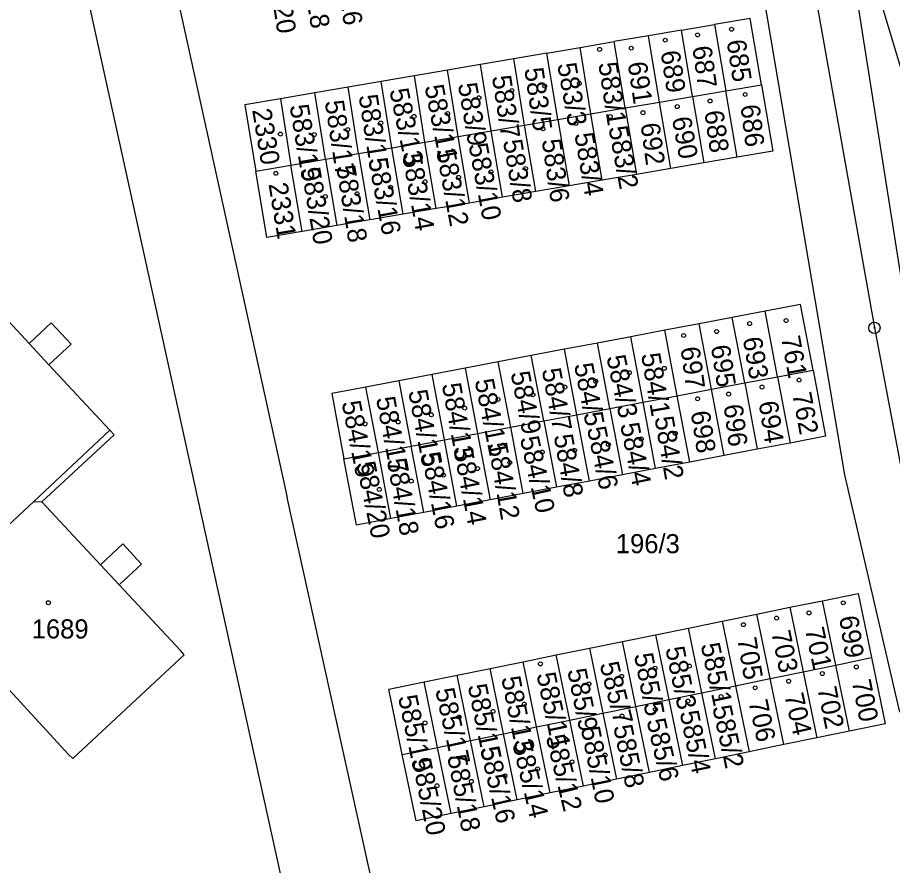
# Model space of a CAD drawing. Extents: x -735249 to -729401, y -1124843 to -1121828.
# Drawn here: x -732956.9 to -732879.1, y -1123958.8 to -1123883.4 of the extents above; entities that cross this region are included whole.
import ezdxf

# ---------------------------------------------------------------- set-up
doc = ezdxf.new("R2010")
doc.units = 0
for name, color, linetype in [('Vrstva 1', 7, 'Continuous'), ('Vrstva 16', 7, 'Continuous'), ('Vrstva 18', 7, 'Continuous'), ('Vrstva 19', 7, 'Continuous'), ('Vrstva 25', 7, 'Continuous'), ('Vrstva 4', 7, 'Continuous')]:
    doc.layers.add(name, color=color, linetype=linetype)

msp = doc.modelspace()

# ---------------------------------------------------------------- linework, layer by layer
at = {"layer": 'Vrstva 1'}
for points in [[(-732886.84, -1123876.47), (-732880.71, -1123910.98), (-732875.49, -1123938.55)], [(-732883.18, -1123876.03), (-732877.7, -1123910.61)], [(-732881.98, -1123875.88), (-732871.76, -1123909.89)], [(-732878.45, -1123945.16), (-732883.33, -1123924.04), (-732891.19, -1123877.61)], [(-732942.93, -1123880.58), (-732932.93, -1123926.08)], [(-732940.57, -1123927.62), (-732950.53, -1123882.29)], [(-732891.77, -1123883.46), (-732894.93, -1123884)], [(-732890.77, -1123889.36), (-732891.77, -1123883.46)], [(-732897.86, -1123884.5), (-732894.93, -1123884)], [(-732894.93, -1123884), (-732893.94, -1123889.9)], [(-732900.82, -1123885.01), (-732903.85, -1123885.53)], [(-732897.86, -1123884.5), (-732900.82, -1123885.01)], [(-732899.83, -1123890.91), (-732900.82, -1123885.01)], [(-732896.88, -1123890.41), (-732897.86, -1123884.5)], [(-732906.88, -1123886.05), (-732903.85, -1123885.53)], [(-732902.88, -1123891.43), (-732903.85, -1123885.53)], [(-732909.84, -1123886.55), (-732912.79, -1123887.06)], [(-732909.84, -1123886.55), (-732906.88, -1123886.05)], [(-732908.88, -1123892.46), (-732909.84, -1123886.55)], [(-732905.93, -1123891.95), (-732906.88, -1123886.05)], [(-732912.79, -1123887.06), (-732915.76, -1123887.57)], [(-732911.84, -1123892.96), (-732912.79, -1123887.06)], [(-732918.68, -1123888.07), (-732921.63, -1123888.57)], [(-732915.76, -1123887.57), (-732918.68, -1123888.07)], [(-732917.74, -1123893.97), (-732918.68, -1123888.07)], [(-732914.8, -1123893.47), (-732915.76, -1123887.57)], [(-732921.63, -1123888.57), (-732924.57, -1123889.07)], [(-732920.7, -1123894.47), (-732921.63, -1123888.57)], [(-732927.52, -1123889.58), (-732930.47, -1123890.08)], [(-732924.57, -1123889.07), (-732927.52, -1123889.58)], [(-732926.6, -1123895.48), (-732927.52, -1123889.58)], [(-732923.64, -1123894.98), (-732924.57, -1123889.07)], [(-732893.94, -1123889.9), (-732890.77, -1123889.36)], [(-732890.77, -1123889.36), (-732889.76, -1123895.27)], [(-732930.47, -1123890.08), (-732933.54, -1123890.61)], [(-732929.54, -1123895.98), (-732930.47, -1123890.08)], [(-732899.83, -1123890.91), (-732896.88, -1123890.41)], [(-732896.88, -1123890.41), (-732893.94, -1123889.9)], [(-732896.88, -1123890.41), (-732895.87, -1123896.31)], [(-732892.93, -1123895.81), (-732893.94, -1123889.9)], [(-732933.54, -1123890.61), (-732936.7, -1123891.15)], [(-732936.7, -1123891.15), (-732935.72, -1123897.05)], [(-732933.54, -1123890.61), (-732932.62, -1123896.51)], [(-732902.88, -1123891.43), (-732899.83, -1123890.91)], [(-732898.82, -1123896.82), (-732899.83, -1123890.91)], [(-732908.88, -1123892.46), (-732905.93, -1123891.95)], [(-732905.93, -1123891.95), (-732902.88, -1123891.43)], [(-732904.92, -1123897.86), (-732905.93, -1123891.95)], [(-732902.88, -1123891.43), (-732901.87, -1123897.34)], [(-732911.84, -1123892.96), (-732908.88, -1123892.46)], [(-732908.88, -1123892.46), (-732907.87, -1123898.36)], [(-732917.74, -1123893.97), (-732914.8, -1123893.47)], [(-732914.8, -1123893.47), (-732911.84, -1123892.96)], [(-732913.79, -1123899.37), (-732914.8, -1123893.47)], [(-732910.83, -1123898.87), (-732911.84, -1123892.96)], [(-732920.7, -1123894.47), (-732917.74, -1123893.97)], [(-732916.73, -1123899.88), (-732917.74, -1123893.97)], [(-732926.6, -1123895.48), (-732923.64, -1123894.98)], [(-732923.64, -1123894.98), (-732920.7, -1123894.47)], [(-732922.63, -1123900.88), (-732923.64, -1123894.98)], [(-732919.69, -1123900.38), (-732920.7, -1123894.47)], [(-732929.54, -1123895.98), (-732926.6, -1123895.48)], [(-732926.6, -1123895.48), (-732925.59, -1123901.39)], [(-732892.93, -1123895.81), (-732895.87, -1123896.31)], [(-732889.76, -1123895.27), (-732892.93, -1123895.81)], [(-732935.72, -1123897.05), (-732932.62, -1123896.51)], [(-732932.62, -1123896.51), (-732929.54, -1123895.98)], [(-732931.61, -1123902.42), (-732932.62, -1123896.51)], [(-732929.54, -1123895.98), (-732928.53, -1123901.89)], [(-732895.87, -1123896.31), (-732898.82, -1123896.82)], [(-732934.74, -1123902.95), (-732935.72, -1123897.05)], [(-732901.87, -1123897.34), (-732904.92, -1123897.86)], [(-732898.82, -1123896.82), (-732901.87, -1123897.34)], [(-732904.92, -1123897.86), (-732907.87, -1123898.36)], [(-732910.83, -1123898.87), (-732913.79, -1123899.37)], [(-732907.87, -1123898.36), (-732910.83, -1123898.87)], [(-732913.79, -1123899.37), (-732916.73, -1123899.88)], [(-732919.69, -1123900.38), (-732922.63, -1123900.88)], [(-732916.73, -1123899.88), (-732919.69, -1123900.38)], [(-732922.63, -1123900.88), (-732925.59, -1123901.39)], [(-732928.53, -1123901.89), (-732931.61, -1123902.42)], [(-732925.59, -1123901.39), (-732928.53, -1123901.89)], [(-732931.61, -1123902.42), (-732934.74, -1123902.95)], [(-732961.35, -1123906.5), (-732955.9, -1123912.36)], [(-732887.28, -1123908.9), (-732890.43, -1123909.5)], [(-732886.17, -1123914.73), (-732887.28, -1123908.9)], [(-732890.43, -1123909.5), (-732893.36, -1123910.05)], [(-732889.32, -1123915.33), (-732890.43, -1123909.5)], [(-732955.9, -1123912.36), (-732953.93, -1123910.53)], [(-732953.93, -1123910.53), (-732952.15, -1123912.43)], [(-732896.31, -1123910.61), (-732899.36, -1123911.19)], [(-732893.36, -1123910.05), (-732896.31, -1123910.61)], [(-732895.2, -1123916.44), (-732896.31, -1123910.61)], [(-732892.25, -1123915.88), (-732893.36, -1123910.05)], [(-732899.36, -1123911.19), (-732902.39, -1123911.77)], [(-732898.25, -1123917.02), (-732899.36, -1123911.19)], [(-732902.39, -1123911.77), (-732905.34, -1123912.33)], [(-732901.29, -1123917.59), (-732902.39, -1123911.77)], [(-732952.15, -1123912.43), (-732954.13, -1123914.27)], [(-732908.28, -1123912.88), (-732911.23, -1123913.44)], [(-732905.34, -1123912.33), (-732908.28, -1123912.88)], [(-732907.17, -1123918.71), (-732908.28, -1123912.88)], [(-732904.24, -1123918.15), (-732905.34, -1123912.33)], [(-732911.23, -1123913.44), (-732914.19, -1123914.01)], [(-732910.1, -1123919.26), (-732911.23, -1123913.44)], [(-732954.13, -1123914.27), (-732948.71, -1123920.08)], [(-732917.12, -1123914.56), (-732920.06, -1123915.12)], [(-732914.19, -1123914.01), (-732917.12, -1123914.56)], [(-732917.12, -1123914.56), (-732916.01, -1123920.38)], [(-732913.05, -1123919.82), (-732914.19, -1123914.01)], [(-732920.06, -1123915.12), (-732923, -1123915.68)], [(-732918.96, -1123920.94), (-732920.06, -1123915.12)], [(-732892.25, -1123915.88), (-732889.32, -1123915.33)], [(-732889.32, -1123915.33), (-732886.17, -1123914.73)], [(-732889.32, -1123915.33), (-732888.2, -1123921.22)], [(-732886.17, -1123914.73), (-732885.05, -1123920.62)], [(-732923, -1123915.68), (-732925.95, -1123916.24)], [(-732923, -1123915.68), (-732921.9, -1123921.5)], [(-732895.2, -1123916.44), (-732892.25, -1123915.88)], [(-732892.25, -1123915.88), (-732891.14, -1123921.77)], [(-732925.95, -1123916.24), (-732928.97, -1123916.81)], [(-732928.97, -1123916.81), (-732927.89, -1123922.63)], [(-732924.83, -1123922.05), (-732925.95, -1123916.24)], [(-732898.25, -1123917.02), (-732895.2, -1123916.44)], [(-732894.08, -1123922.33), (-732895.2, -1123916.44)], [(-732904.24, -1123918.15), (-732901.29, -1123917.59)], [(-732901.29, -1123917.59), (-732898.25, -1123917.02)], [(-732900.18, -1123923.48), (-732901.29, -1123917.59)], [(-732897.13, -1123922.91), (-732898.25, -1123917.02)], [(-732907.17, -1123918.71), (-732904.24, -1123918.15)], [(-732904.24, -1123918.15), (-732903.12, -1123924.04)], [(-732913.05, -1123919.82), (-732910.1, -1123919.26)], [(-732910.1, -1123919.26), (-732907.17, -1123918.71)], [(-732910.1, -1123919.26), (-732908.98, -1123925.15)], [(-732906.06, -1123924.6), (-732907.17, -1123918.71)], [(-732916.01, -1123920.38), (-732913.05, -1123919.82)], [(-732911.94, -1123925.71), (-732913.05, -1123919.82)], [(-732948.34, -1123920.48), (-732954.76, -1123926.44)], [(-732948.71, -1123920.08), (-732948.34, -1123920.48)], [(-732918.96, -1123920.94), (-732916.01, -1123920.38)], [(-732916.01, -1123920.38), (-732914.89, -1123926.27)], [(-732885.05, -1123920.62), (-732888.2, -1123921.22)], [(-732924.83, -1123922.05), (-732921.9, -1123921.5)], [(-732921.9, -1123921.5), (-732918.96, -1123920.94)], [(-732920.78, -1123927.39), (-732921.9, -1123921.5)], [(-732917.85, -1123926.83), (-732918.96, -1123920.94)], [(-732888.2, -1123921.22), (-732891.14, -1123921.77)], [(-732927.89, -1123922.63), (-732924.83, -1123922.05)], [(-732923.72, -1123927.94), (-732924.83, -1123922.05)], [(-732894.08, -1123922.33), (-732897.13, -1123922.91)], [(-732891.14, -1123921.77), (-732894.08, -1123922.33)], [(-732926.77, -1123928.52), (-732927.89, -1123922.63)], [(-732897.13, -1123922.91), (-732900.18, -1123923.48)], [(-732900.18, -1123923.48), (-732903.12, -1123924.04)], [(-732906.06, -1123924.6), (-732908.98, -1123925.15)], [(-732903.12, -1123924.04), (-732906.06, -1123924.6)], [(-732908.98, -1123925.15), (-732911.94, -1123925.71)], [(-732920.95, -1123980.45), (-732932.93, -1123926.08)], [(-732914.89, -1123926.27), (-732917.85, -1123926.83)], [(-732911.94, -1123925.71), (-732914.89, -1123926.27)], [(-732958.21, -1123928.96), (-732955.46, -1123926.41)], [(-732955.46, -1123926.41), (-732954.76, -1123926.44)], [(-732949.54, -1123932.04), (-732954.76, -1123926.44)], [(-732917.85, -1123926.83), (-732920.78, -1123927.39)], [(-732922.61, -1124019.23), (-732926.9, -1124007.81), (-732928.66, -1124002.14), (-732929.71, -1123998.65), (-732925.26, -1123994.52), (-732927.83, -1123984.85), (-732930.58, -1123972.96), (-732940.57, -1123927.62)], [(-732920.78, -1123927.39), (-732923.72, -1123927.94)], [(-732923.72, -1123927.94), (-732926.77, -1123928.52)], [(-732947.57, -1123930.2), (-732949.54, -1123932.04)], [(-732945.9, -1123931.99), (-732947.57, -1123930.2)], [(-732947.88, -1123933.82), (-732945.9, -1123931.99)], [(-732942.44, -1123939.68), (-732947.88, -1123933.82)], [(-732885.32, -1123935.24), (-732882.15, -1123934.59)], [(-732882.15, -1123934.59), (-732880.98, -1123940.3)], [(-732964.95, -1123935.26), (-732952.38, -1123948.92)], [(-732888.24, -1123935.83), (-732885.32, -1123935.24)], [(-732884.14, -1123940.96), (-732885.32, -1123935.24)], [(-732891.17, -1123936.43), (-732888.24, -1123935.83)], [(-732888.24, -1123935.83), (-732887.05, -1123941.56)], [(-732897.24, -1123937.67), (-732894.26, -1123937.06)], [(-732894.26, -1123937.06), (-732891.17, -1123936.43)], [(-732894.26, -1123937.06), (-732893.07, -1123942.81)], [(-732889.99, -1123942.17), (-732891.17, -1123936.43)], [(-732900.18, -1123938.27), (-732897.24, -1123937.67)], [(-732896.06, -1123943.42), (-732897.24, -1123937.67)], [(-732903.12, -1123938.87), (-732900.18, -1123938.27)], [(-732900.18, -1123938.27), (-732899, -1123944.03)], [(-732909.01, -1123940.07), (-732906.06, -1123939.47)], [(-732906.06, -1123939.47), (-732903.12, -1123938.87)], [(-732906.06, -1123939.47), (-732904.87, -1123945.25)], [(-732901.93, -1123944.64), (-732903.12, -1123938.87)], [(-732952.01, -1123949.26), (-732942.1, -1123940.05)], [(-732942.1, -1123940.05), (-732942.44, -1123939.68)], [(-732911.96, -1123940.67), (-732909.01, -1123940.07)], [(-732907.81, -1123945.85), (-732909.01, -1123940.07)], [(-732914.9, -1123941.27), (-732911.96, -1123940.67)], [(-732910.76, -1123946.46), (-732911.96, -1123940.67)], [(-732887.05, -1123941.56), (-732884.14, -1123940.96)], [(-732884.14, -1123940.96), (-732880.98, -1123940.3)], [(-732882.92, -1123946.83), (-732884.14, -1123940.96)], [(-732880.98, -1123940.3), (-732879.76, -1123946.18)], [(-732917.82, -1123941.87), (-732914.9, -1123941.27)], [(-732913.7, -1123947.07), (-732914.9, -1123941.27)], [(-732889.99, -1123942.17), (-732887.05, -1123941.56)], [(-732887.05, -1123941.56), (-732885.83, -1123947.44)], [(-732923.89, -1123943.11), (-732920.77, -1123942.47)], [(-732920.77, -1123942.47), (-732917.82, -1123941.87)], [(-732919.57, -1123948.29), (-732920.77, -1123942.47)], [(-732916.63, -1123947.68), (-732917.82, -1123941.87)], [(-732893.07, -1123942.81), (-732889.99, -1123942.17)], [(-732888.77, -1123948.04), (-732889.99, -1123942.17)], [(-732922.7, -1123948.93), (-732923.89, -1123943.11)], [(-732896.06, -1123943.42), (-732893.07, -1123942.81)], [(-732893.07, -1123942.81), (-732891.85, -1123948.68)], [(-732901.93, -1123944.64), (-732899, -1123944.03)], [(-732899, -1123944.03), (-732896.06, -1123943.42)], [(-732899, -1123944.03), (-732897.78, -1123949.91)], [(-732894.84, -1123949.3), (-732896.06, -1123943.42)], [(-732904.87, -1123945.25), (-732901.93, -1123944.64)], [(-732900.72, -1123950.52), (-732901.93, -1123944.64)], [(-732907.81, -1123945.85), (-732904.87, -1123945.25)], [(-732904.87, -1123945.25), (-732903.66, -1123951.12)], [(-732913.7, -1123947.07), (-732910.76, -1123946.46)], [(-732910.76, -1123946.46), (-732907.81, -1123945.85)], [(-732909.54, -1123952.34), (-732910.76, -1123946.46)], [(-732906.59, -1123951.73), (-732907.81, -1123945.85)], [(-732879.76, -1123946.18), (-732882.92, -1123946.83)], [(-732916.63, -1123947.68), (-732913.7, -1123947.07)], [(-732912.48, -1123952.95), (-732913.7, -1123947.07)], [(-732882.92, -1123946.83), (-732885.83, -1123947.44)], [(-732919.57, -1123948.29), (-732916.63, -1123947.68)], [(-732915.42, -1123953.56), (-732916.63, -1123947.68)], [(-732888.77, -1123948.04), (-732891.85, -1123948.68)], [(-732885.83, -1123947.44), (-732888.77, -1123948.04)], [(-732922.7, -1123948.93), (-732919.57, -1123948.29)], [(-732918.36, -1123954.16), (-732919.57, -1123948.29)], [(-732891.85, -1123948.68), (-732894.84, -1123949.3)], [(-732952.38, -1123948.92), (-732952.01, -1123949.26)], [(-732921.48, -1123954.81), (-732922.7, -1123948.93)], [(-732894.84, -1123949.3), (-732897.78, -1123949.91)], [(-732897.78, -1123949.91), (-732900.72, -1123950.52)], [(-732903.66, -1123951.12), (-732906.59, -1123951.73)], [(-732900.72, -1123950.52), (-732903.66, -1123951.12)], [(-732906.59, -1123951.73), (-732909.54, -1123952.34)], [(-732909.54, -1123952.34), (-732912.48, -1123952.95)], [(-732912.48, -1123952.95), (-732915.42, -1123953.56)], [(-732918.36, -1123954.16), (-732921.48, -1123954.81)], [(-732915.42, -1123953.56), (-732918.36, -1123954.16)]]:
    msp.add_lwpolyline(points, dxfattribs=at)
at = {"layer": 'Vrstva 25'}
for centre, radius in [((-732893.42, -1123884.43), 0.175), ((-732896.44, -1123884.93), 0.175), ((-732899.32, -1123885.4), 0.175), ((-732905.16, -1123886.22), 0.175), ((-732902.34, -1123886.11), 0.175), ((-732912.96, -1123889.88), 0.175), ((-732910.03, -1123889.49), 0.175), ((-732906.96, -1123889.25), 0.175), ((-732915.89, -1123890.52), 0.175), ((-732892.21, -1123890.23), 0.175), ((-732898.25, -1123891.31), 0.175), ((-732895.33, -1123890.81), 0.175), ((-732921.65, -1123892.18), 0.175), ((-732918.67, -1123891.93), 0.175), ((-732904.2, -1123892.19), 0.175), ((-732901.3, -1123891.85), 0.175), ((-732924.62, -1123892.76), 0.175), ((-732907.26, -1123892.81), 0.175), ((-732933.54, -1123893.75), 0.175), ((-732927.55, -1123893.35), 0.175), ((-732910.19, -1123893.28), 0.175), ((-732930.53, -1123893.79), 0.175), ((-732911.74, -1123896.81), 0.175), ((-732933.95, -1123897.24), 0.175), ((-732917.7, -1123897.6), 0.175), ((-732914.82, -1123897.11), 0.175), ((-732920.67, -1123897.99), 0.175), ((-732926.72, -1123899.06), 0.175), ((-732923.75, -1123898.47), 0.175), ((-732929.55, -1123899.3), 0.175), ((-732891.81, -1123910.6), 0.175), ((-732888.57, -1123910.33), 0.175), ((-732880.71, -1123910.98), 0.5), ((-732897.68, -1123911.66), 0.175), ((-732894.75, -1123911.31), 0.175), ((-732880.71, -1123910.98), 0.032), ((-732899.4, -1123914.58), 0.175), ((-732902.51, -1123914.97), 0.175), ((-732908.24, -1123916.25), 0.175), ((-732905.5, -1123915.73), 0.175), ((-732890.71, -1123916.25), 0.175), ((-732887.41, -1123915.63), 0.175), ((-732911.09, -1123916.93), 0.175), ((-732893.68, -1123916.87), 0.175), ((-732914.18, -1123917.35), 0.175), ((-732896.44, -1123917.29), 0.175), ((-732917.15, -1123918.12), 0.175), ((-732923.07, -1123919.35), 0.175), ((-732920.12, -1123918.71), 0.175), ((-732926.01, -1123919.52), 0.175), ((-732901.45, -1123920.86), 0.175), ((-732898.43, -1123920.36), 0.175), ((-732904.37, -1123921.36), 0.175), ((-732910.26, -1123922.03), 0.175), ((-732907.38, -1123921.88), 0.175), ((-732913.14, -1123922.96), 0.175), ((-732919.05, -1123924.07), 0.175), ((-732916.01, -1123923.49), 0.175), ((-732921.9, -1123924.61), 0.175), ((-732924.75, -1123925.35), 0.175), ((-732954.18, -1123935.42), 0.175), ((-732883.49, -1123935.43), 0.175), ((-732886.53, -1123936.33), 0.175), ((-732889.42, -1123936.79), 0.175), ((-732892.36, -1123937.37), 0.175), ((-732894.23, -1123940.43), 0.175), ((-732910.42, -1123940.86), 0.175), ((-732897.17, -1123941.06), 0.175), ((-732882.32, -1123941.13), 0.175), ((-732903.2, -1123941.97), 0.175), ((-732900.22, -1123941.25), 0.175), ((-732885.35, -1123941.72), 0.175), ((-732906.11, -1123942.64), 0.175), ((-732888.34, -1123942.4), 0.175), ((-732891.32, -1123942.99), 0.175), ((-732897.3, -1123944.17), 0.175), ((-732894.35, -1123943.76), 0.175), ((-732914.63, -1123945.09), 0.175), ((-732911.86, -1123944.44), 0.175), ((-732900.19, -1123944.91), 0.175), ((-732917.65, -1123945.59), 0.175), ((-732903.16, -1123945.5), 0.175), ((-732920.68, -1123946.11), 0.175), ((-732904.67, -1123948.97), 0.175), ((-732907.61, -1123949.57), 0.175), ((-732910.67, -1123950.2), 0.175), ((-732916.56, -1123951.31), 0.175), ((-732913.57, -1123950.82), 0.175), ((-732919.62, -1123951.7), 0.175)]:
    msp.add_circle(centre, radius, dxfattribs=at)
at = {"layer": 'Vrstva 4'}
for points in [[(-732955.9, -1123912.36), (-732954.13, -1123914.27)], [(-732955.46, -1123926.41), (-732948.71, -1123920.08)], [(-732949.54, -1123932.04), (-732947.88, -1123933.82)]]:
    msp.add_lwpolyline(points, dxfattribs=at)

# ---------------------------------------------------------------- texts
at = {"layer": 'Vrstva 16'}
for s, rotation, p in [('582/16', 277.90221, (-732928.844, -1123877.284)), ('582/20', 278.90222, (-732934.868, -1123878.039)), ('582/18', 279.40222, (-732931.925, -1123877.606))]:
    msp.add_text(s, height=1.7, rotation=rotation, dxfattribs=at).set_placement(p)
at = {"layer": 'Vrstva 18'}
msp.add_text('196/3', height=1.7, dxfattribs=at).set_placement((-732903.71, -1123931.02))
at = {"layer": 'Vrstva 19'}
for s, rotation, p in [('685', 278.80222, (-732893.862, -1123885.467)), ('689', 278.70222, (-732899.733, -1123886.437)), ('687', 278.10221, (-732896.914, -1123886.009)), ('691', 278.10221, (-732902.654, -1123887.419)), ('583/5', 278.40221, (-732911.853, -1123887.948)), ('583/3', 280.20223, (-732908.928, -1123887.551)), ('583/1', 278.70222, (-732905.273, -1123887.467)), ('583/7', 278.70222, (-732914.733, -1123888.637)), ('583/13', 281.70224, (-732923.854, -1123889.845)), ('583/11', 281.10224, (-732920.726, -1123889.507)), ('583/9', 279.70222, (-732917.76, -1123889.313)), ('583/15', 278.90222, (-732926.592, -1123890.346)), ('583/19', 279.50222, (-732932.73, -1123891.234)), ('583/17', 278.60222, (-732929.603, -1123890.847)), ('686', 277.1022, (-732892.627, -1123891.213)), ('2330', 279.40222, (-732936.061, -1123891.604)), ('688', 278.10221, (-732895.844, -1123891.749)), ('692', 277.70221, (-732901.516, -1123892.851)), ('690', 280.20223, (-732898.728, -1123892.341)), ('583/2', 280.40223, (-732904.368, -1123893.17)), ('583/8', 279.70222, (-732913.75, -1123894.353)), ('583/6', 278.30221, (-732910.304, -1123894.289)), ('583/4', 279.70222, (-732907.4, -1123893.753)), ('583/12', 280.50223, (-732919.697, -1123895.23)), ('583/10', 280.70223, (-732916.817, -1123894.699)), ('583/16', 280.70223, (-732925.747, -1123896.009)), ('583/14', 280.20223, (-732922.718, -1123895.621)), ('583/18', 279.30222, (-732928.591, -1123896.635)), ('583/20', 279.70222, (-732931.71, -1123896.833)), ('2331', 279.50222, (-732934.61, -1123898.194)), ('693', 279.80223, (-732892.429, -1123911.923)), ('761', 280.50223, (-732889.027, -1123911.84)), ('697', 277.90221, (-732897.965, -1123912.76)), ('695', 279.00222, (-732895.272, -1123912.616)), ('584/3', 281.90224, (-732904.554, -1123913.564)), ('584/1', 279.70222, (-732901.47, -1123913.343)), ('584/7', 280.70223, (-732910.307, -1123914.709)), ('584/5', 281.00224, (-732907.436, -1123914.258)), ('584/9', 281.20224, (-732913.075, -1123914.997)), ('584/13', 280.30223, (-732919.188, -1123916.021)), ('584/11', 281.30224, (-732916.275, -1123915.666)), ('584/15', 280.70223, (-732922.177, -1123916.629)), ('762', 280.60223, (-732888.027, -1123916.859)), ('584/19', 281.10224, (-732928.106, -1123917.617)), ('584/17', 280.70223, (-732925.047, -1123917.239)), ('694', 278.80222, (-732891.012, -1123917.597)), ('698', 279.00222, (-732897.062, -1123918.476)), ('696', 277.20221, (-732894.127, -1123917.863)), ('584/2', 279.80223, (-732900.279, -1123918.973)), ('584/6', 281.70224, (-732906.284, -1123919.915)), ('584/4', 281.50224, (-732903.335, -1123919.576)), ('584/10', 282.50225, (-732912.252, -1123920.791)), ('584/8', 280.10223, (-732909.239, -1123920.571)), ('584/12', 279.90222, (-732915.089, -1123921.302)), ('584/16', 281.20224, (-732921.025, -1123922.177)), ('584/14', 280.90223, (-732918.156, -1123921.798)), ('584/20', 281.70224, (-732926.814, -1123923.025)), ('584/18', 280.20223, (-732924.088, -1123922.721)), ('699', 278.40221, (-732883.853, -1123936.688)), ('703', 281.60224, (-732889.894, -1123938.055)), ('701', 281.90224, (-732886.904, -1123937.784)), ('705', 279.70222, (-732892.92, -1123938.633)), ('585/3', 281.70224, (-732899.314, -1123939.475)), ('585/1', 282.10224, (-732896.173, -1123939.163)), ('585/5', 281.10224, (-732902.106, -1123940.047)), ('585/7', 283.80226, (-732905.159, -1123940.876)), ('585/11', 281.90224, (-732910.774, -1123941.784)), ('585/9', 281.30224, (-732908.035, -1123941.426)), ('585/13', 281.20224, (-732913.905, -1123942.107)), ('700', 281.30224, (-732882.735, -1123942.416)), ('585/17', 282.30224, (-732919.782, -1123943.182)), ('585/15', 281.50224, (-732916.885, -1123942.806)), ('704', 282.60225, (-732888.732, -1123943.641)), ('702', 281.40224, (-732885.795, -1123943.036)), ('585/19', 281.80224, (-732923.084, -1123943.794)), ('706', 282.10224, (-732891.923, -1123944.213)), ('585/2', 282.20224, (-732895.133, -1123944.713)), ('585/6', 283.00225, (-732900.991, -1123945.899)), ('585/4', 281.70224, (-732898.044, -1123945.175)), ('585/10', 281.40224, (-732906.835, -1123946.586)), ('585/8', 281.60224, (-732903.944, -1123946.435)), ('585/12', 283.50226, (-732909.949, -1123947.347)), ('585/14', 283.30225, (-732912.93, -1123947.928)), ('585/16', 282.80225, (-732915.801, -1123948.39)), ('585/20', 281.50224, (-732921.855, -1123949.426)), ('585/18', 281.10224, (-732918.716, -1123949.087))]:
    msp.add_text(s, height=1.7, rotation=rotation, dxfattribs=at).set_placement(p)
msp.add_text('1689', height=1.7, dxfattribs=at).set_placement((-732955.66, -1123938.6))

doc.saveas('drawing.dxf')
